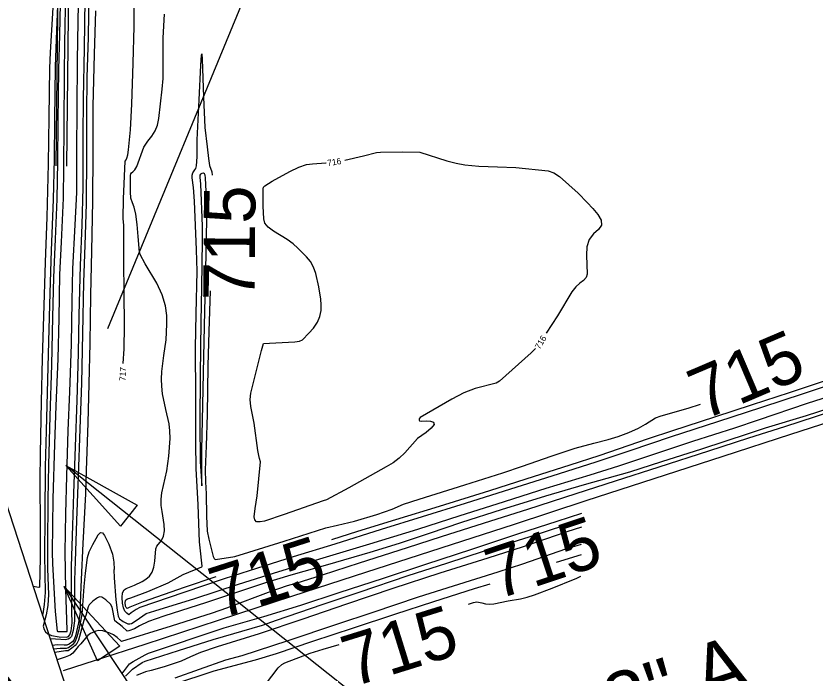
# Model space of a CAD drawing. Extents: x -468563856 to 36492962, y -306094093 to 11899197.
# Drawn here: x 1819091 to 1819604, y 530139 to 530560 of the extents above; entities that cross this region are included whole.
import ezdxf

# ---------------------------------------------------------------- set-up
doc = ezdxf.new("R2010")
doc.units = 0
for name, color, linetype in [('DT_X_Contour_Minor', 7, 'Continuous'), ('DT_X_Terrain_Ground_Line', 7, 'Continuous'), ('Level 14', 7, 'Continuous'), ('Level 19', 7, 'Continuous'), ('Level 40', 7, 'Continuous'), ('Level 56', 7, 'Continuous'), ('SC_Scratch1', 7, 'Continuous')]:
    doc.layers.add(name, color=color, linetype=linetype)

msp = doc.modelspace()

# ---------------------------------------------------------------- linework, layer by layer
at = {"layer": 'DT_X_Contour_Minor'}
for points in [[(1819123.04, 530576.32), (1819122.55, 530542.42), (1819122.31, 530522.38), (1819122, 530490.35), (1819121.92, 530463.26), (1819121.73, 530443.28), (1819120.3, 530415.01), (1819119.32, 530394.3), (1819118.81, 530366.36), (1819118.19, 530340.29), (1819117, 530310.12), (1819116.14, 530285.53), (1819115.1, 530250.53), (1819114.55, 530216.45), (1819114.82, 530208.84), (1819116.5, 530178.28), (1819117.79, 530165.64), (1819118.29, 530165.56), (1819124.21, 530165.45), (1819124.21, 530166.38), (1819123.28, 530192.74), (1819122.92, 530216.31), (1819123.35, 530241.23), (1819123.89, 530265.12), (1819124.89, 530294.25), (1819125.83, 530319.08), (1819126.97, 530349.68), (1819127.46, 530377.53), (1819127.9, 530398.02), (1819129.36, 530426.26), (1819130.32, 530446.96), (1819130.44, 530474.05), (1819130.58, 530500.07), (1819130.9, 530531.68), (1819131.23, 530556.26), (1819131.8, 530590.99)], [(1819120, 530578.27), (1819119.3, 530547.97), (1819118.61, 530525.83), (1819118.2, 530492.3), (1819118.02, 530466.77), (1819117.61, 530442.7), (1819116.5, 530416.88), (1819115.47, 530392.41), (1819114.87, 530366.91), (1819114.09, 530336.37), (1819112.99, 530303.55), (1819112.14, 530272.28), (1819111.86, 530250.18), (1819111.54, 530220.56), (1819111.57, 530205.58), (1819112.19, 530189.28), (1819111.87, 530182.1), (1819110.63, 530176.17), (1819108.87, 530169.01), (1819109.54, 530166.88), (1819110.41, 530165.36), (1819111.89, 530163.98), (1819114.09, 530163.04), (1819119.13, 530162.16), (1819123.77, 530161.98), (1819124.97, 530162.37), (1819125.99, 530163.4), (1819126.77, 530166.01), (1819127.35, 530170.99), (1819127.29, 530178.08), (1819126.89, 530195.65), (1819126.99, 530207.23), (1819127.73, 530233.49), (1819128.41, 530254.03), (1819129.52, 530284.05), (1819130.55, 530313.47), (1819131.51, 530343.93), (1819131.97, 530368.37), (1819132.72, 530400.11), (1819133.86, 530426.25), (1819134.41, 530450.01), (1819134.55, 530482.97), (1819134.67, 530506.95), (1819135.25, 530539.31), (1819135.82, 530570.8)], [(1819138.12, 530576.66), (1819137.58, 530546.32), (1819136.91, 530520.91), (1819136.62, 530497.38), (1819136.57, 530471.07), (1819136.29, 530439.63), (1819135.56, 530413.23), (1819134.74, 530389.39), (1819134.1, 530356.54), (1819133.38, 530324.78), (1819132.38, 530295.36), (1819131.36, 530265.05), (1819130.14, 530236.61), (1819129.28, 530210.39), (1819128.84, 530198.51), (1819128.84, 530187.24), (1819128.96, 530172.36), (1819128.04, 530166.21), (1819126.9, 530162.4), (1819125.89, 530161.24), (1819124.83, 530160.54), (1819123.12, 530160.18), (1819120.11, 530160.35), (1819113.31, 530160.92)], [(1819160.21, 530337.32), (1819160.67, 530346.75), (1819160.95, 530361.36), (1819160.79, 530383.07), (1819160.62, 530402.24), (1819160.49, 530425.65), (1819160.01, 530430.17), (1819160.28, 530442.86), (1819161.4, 530467.08), (1819162.05, 530467.79), (1819162.52, 530468.89), (1819163.05, 530470.93), (1819163.61, 530474.34), (1819164.77, 530487.02), (1819165.67, 530503.5), (1819166.5, 530529.84), (1819167.21, 530553.27), (1819167.2, 530574.75)], [(1819108.42, 530175.98), (1819108.71, 530176.91), (1819109.73, 530182.84), (1819110.24, 530190.48), (1819109.93, 530214.36), (1819110.2, 530239.26), (1819110.33, 530271.05), (1819110.89, 530294.17), (1819111.78, 530326.83), (1819112.53, 530351.29), (1819113.27, 530382.52), (1819114.25, 530409.79), (1819115.54, 530442.4), (1819116.08, 530468.52), (1819116.31, 530493.28), (1819116.76, 530527.55), (1819117.67, 530550.74), (1819118.37, 530572.31)], [(1819114.91, 530565.52), (1819113.34, 530536.57), (1819112.93, 530526.55), (1819112.51, 530495.24), (1819112.03, 530465.36), (1819111.14, 530430.99), (1819110.17, 530402.24), (1819108.96, 530367.73), (1819108.21, 530340.46), (1819107.5, 530312.82), (1819106.86, 530279.6), (1819106.72, 530262.54), (1819106.94, 530231.76), (1819106.86, 530212.96), (1819106.4, 530193.9), (1819106.12, 530193.7), (1819102.44, 530194.41)], [(1819142.3, 530563.39), (1819141.59, 530535.57), (1819140.67, 530502.31), (1819140.65, 530472.82), (1819140.39, 530441.3), (1819139.82, 530409.57), (1819139.25, 530381.18), (1819138.65, 530350.38), (1819138.08, 530324.26), (1819137.45, 530299.3), (1819136.47, 530268.75), (1819135.87, 530253.83), (1819134.31, 530221.88), (1819133.1, 530198.75), (1819132.55, 530183.58), (1819132.53, 530177.88), (1819131.5, 530171.07), (1819129.61, 530162.76), (1819128.7, 530160.4), (1819127.85, 530159.17), (1819125.49, 530157.33), (1819124.01, 530156.69), (1819122.21, 530156.72), (1819117.71, 530156.96), (1819114.73, 530156.54)], [(1819188.16, 530268.57), (1819189.35, 530277.85), (1819190.17, 530289.25), (1819190.04, 530294.13), (1819189.51, 530298.55), (1819187.53, 530307.83), (1819185.4, 530317.9), (1819184.82, 530322.66), (1819184.66, 530327.31), (1819184.9, 530332.11), (1819186.27, 530342.46), (1819187.6, 530352.48), (1819188.12, 530362.43), (1819188, 530368.08), (1819187.2, 530374.35), (1819185.18, 530381.27), (1819181.73, 530388.71), (1819174.31, 530401.27), (1819171.04, 530407.08), (1819170.68, 530408.61), (1819169.79, 530418.73), (1819169.16, 530426.35), (1819168.3, 530433.09), (1819167.17, 530437.47), (1819166.01, 530440.37), (1819165.13, 530443.28), (1819164.74, 530447.26), (1819164.86, 530457.74), (1819165, 530458.93), (1819165.45, 530459.56), (1819166.34, 530460.18), (1819167.53, 530461.35), (1819168.82, 530463.59), (1819173.4, 530476), (1819175.86, 530479.76), (1819178.49, 530483.1), (1819180.7, 530486.4), (1819182.09, 530490.04), (1819182.9, 530494.36), (1819185.1, 530513.04), (1819185.67, 530519.94), (1819185.83, 530532.4), (1819185.85, 530546.09), (1819186.52, 530561.25)], [(1819219.44, 530200.61), (1819199.28, 530193.67), (1819172.84, 530184.48), (1819164.43, 530181.1), (1819162.76, 530180.21), (1819162.04, 530180.89), (1819161.68, 530181.67), (1819161.36, 530184.09), (1819161.5, 530185.19), (1819161.86, 530185.88), (1819162.79, 530186.37), (1819165.03, 530186.99), (1819175.82, 530191.19), (1819189.04, 530196.8), (1819198.64, 530202.02), (1819210.55, 530206.98), (1819210.76, 530207.45), (1819209.38, 530219.13), (1819209.07, 530222.89), (1819208.19, 530246.75), (1819206.96, 530269.89), (1819206.71, 530286.45), (1819206.71, 530315.92), (1819206.46, 530347.38), (1819206.91, 530369.04), (1819207.48, 530396.39), (1819207.16, 530410.08), (1819205.84, 530441.29), (1819205.25, 530450.13), (1819204.28, 530456.25), (1819204.38, 530457.96), (1819204.75, 530459.45), (1819205.99, 530461.42), (1819206.65, 530462.32), (1819207.15, 530463.88), (1819207.46, 530469.69), (1819207.57, 530480.55), (1819208.87, 530506.34), (1819209.88, 530528.57), (1819210.28, 530535.02), (1819210.48, 530535.74), (1819210.75, 530532.25), (1819211.53, 530507.92), (1819212.52, 530488.6), (1819213.95, 530476.08), (1819214.88, 530468.69), (1819215.38, 530464.13), (1819216.91, 530460.21), (1819217.14, 530458.08)], [(1819302.25, 530467.6), (1819314.15, 530470.36), (1819322.56, 530472.43), (1819325.11, 530472.74), (1819339.35, 530472.86), (1819350.26, 530472.72), (1819367.62, 530467.17), (1819373.72, 530465.64), (1819379.15, 530464.63), (1819388.26, 530463.76), (1819400.06, 530463.36), (1819411.97, 530462.98), (1819432.54, 530460.81), (1819436.28, 530459.47), (1819439.89, 530457.08), (1819451.79, 530446.49), (1819457.71, 530440.47), (1819461.23, 530436.65), (1819464.42, 530432.8), (1819466.53, 530429.15), (1819466.8, 530425.91), (1819464.81, 530423.14), (1819461.66, 530420.3), (1819458.81, 530416.73), (1819457.39, 530412), (1819457.14, 530406.72), (1819457.7, 530394.65), (1819456.92, 530392.36), (1819455.21, 530390.58), (1819452.88, 530388.81), (1819450.34, 530386.51), (1819447.89, 530383.23), (1819438.57, 530367.92), (1819431.4, 530356.73)], [(1819424.43, 530346.92), (1819421.63, 530344.23), (1819401.35, 530325.98), (1819399.22, 530324.76), (1819385.83, 530321.23), (1819378.57, 530318.39), (1819370.83, 530314.43), (1819350.56, 530302.63), (1819349.98, 530301.85), (1819349.83, 530301.07), (1819350.19, 530300.53), (1819351.12, 530300.41), (1819354.7, 530300.61), (1819357.16, 530300.42), (1819359.1, 530299.7), (1819359.43, 530298.2), (1819357.5, 530295.83), (1819354.31, 530293.17), (1819348.87, 530289.18), (1819340.74, 530280.09), (1819337.01, 530276.52), (1819333.28, 530273.67), (1819328.8, 530270.96), (1819304.8, 530257.7), (1819290.46, 530249.95), (1819288.38, 530249.29), (1819263.36, 530240.46), (1819250.69, 530236.34), (1819247.87, 530235.75), (1819245.65, 530235.87), (1819244.49, 530237.03), (1819244.2, 530239.03), (1819244.82, 530244.35), (1819245.94, 530252.38), (1819248.13, 530274.28), (1819247.58, 530276.42), (1819247, 530278.34), (1819246.36, 530281.63), (1819244.12, 530298.98), (1819242.06, 530309.83), (1819241.61, 530314.3), (1819241.98, 530318.29), (1819248.83, 530345.66), (1819250.01, 530350.11), (1819253.95, 530350.39), (1819270.1, 530351.18), (1819273.2, 530351.6), (1819275, 530352.44), (1819279.22, 530356.63), (1819282.12, 530359.97), (1819284.67, 530363.68), (1819286.27, 530367.45), (1819287.02, 530371.2), (1819287.15, 530374.91), (1819286.89, 530378.59), (1819285.65, 530386.35), (1819283.75, 530395), (1819282.23, 530399.06), (1819280.16, 530402.57), (1819277.68, 530405.66), (1819272.17, 530411.25), (1819269.05, 530413.98), (1819265.34, 530416.71), (1819256.52, 530422.14), (1819253, 530424.7), (1819251.01, 530427.17), (1819250.21, 530429.95), (1819249.9, 530438.18), (1819249.83, 530449.31), (1819249.99, 530450.31), (1819250.96, 530451.23), (1819255.65, 530454.12), (1819266.89, 530460.41), (1819272.81, 530463.19), (1819277.59, 530464.75), (1819281.61, 530465.37), (1819290.07, 530465.86), (1819290.37, 530465.89)], [(1819210.56, 530258.81), (1819210.6, 530281.72), (1819211.27, 530310.48), (1819211.84, 530341.6), (1819212.37, 530370.91), (1819213.03, 530397.35), (1819213.7, 530429.57), (1819213.65, 530439.09), (1819212.97, 530456.39), (1819212.67, 530458.05), (1819212.23, 530458.93), (1819211.69, 530459.26), (1819210.55, 530459.17), (1819209.67, 530458.72), (1819209.26, 530457.92), (1819209.29, 530456.76), (1819209.62, 530452.13), (1819210.68, 530425.27), (1819210.76, 530416.15), (1819210.32, 530386.1), (1819209.86, 530364.05), (1819209.42, 530330.06), (1819209.33, 530299.39), (1819209.45, 530274.42), (1819210.56, 530258.81)], [(1819215.89, 530383.89), (1819214.99, 530357.75), (1819214.35, 530335.73), (1819213.91, 530304.68), (1819213.22, 530284.62), (1819212.68, 530269.23), (1819212.82, 530261.45), (1819213.38, 530253.75), (1819213.55, 530239.53), (1819213.87, 530229.91), (1819214.96, 530224.73), (1819217.88, 530213.61), (1819218.39, 530212.23), (1819219.02, 530211.74), (1819222.08, 530212.07), (1819231.79, 530213.57), (1819240.63, 530216.34), (1819263.37, 530223.5), (1819290.14, 530231.87), (1819297.63, 530233.69), (1819308.35, 530236.15), (1819322.84, 530240.45), (1819332.62, 530243.95), (1819339.87, 530247.08), (1819349.82, 530250.35), (1819379.25, 530259.52), (1819403.49, 530267.17), (1819416.2, 530271.41), (1819434.56, 530278), (1819449.95, 530282.94), (1819461.96, 530286.23), (1819471.16, 530288.52), (1819477.5, 530290.54), (1819484.43, 530293.08), (1819490.62, 530295.79), (1819495.12, 530298.38), (1819501.5, 530302.48), (1819505.06, 530303.83), (1819522.38, 530308.6), (1819530.24, 530311.17)], [(1819735.12, 530365.57), (1819720.1, 530360.98), (1819690.82, 530351.97), (1819665.02, 530343.81), (1819633.43, 530333.77), (1819616.08, 530328.1), (1819587.14, 530318.56), (1819563.46, 530310.78), (1819539.22, 530302.91), (1819512.34, 530294.19), (1819496.73, 530288.95), (1819465.07, 530278.01), (1819446.56, 530272.1), (1819418.4, 530263.17), (1819394.91, 530255.75), (1819362.75, 530245.73), (1819334.71, 530237.16), (1819310.42, 530229.54), (1819293.76, 530224.31)], [(1819625.91, 530327.72), (1819596.04, 530317.94), (1819569.46, 530309.04), (1819541.27, 530299.92), (1819511.55, 530290.3), (1819484.91, 530281.29), (1819463.25, 530274.01), (1819435, 530265.11), (1819408.56, 530256.74), (1819379.45, 530247.52), (1819351.76, 530238.91), (1819325.44, 530230.82), (1819295.73, 530221.59), (1819269.06, 530213.3), (1819240.93, 530204.45), (1819224.86, 530199.21), (1819199.04, 530190.51), (1819170.76, 530180.86), (1819168.36, 530179.71), (1819165.31, 530177.51), (1819163.79, 530176.28), (1819162.37, 530177.21), (1819161.28, 530178.46), (1819160.27, 530180.6), (1819159.59, 530183.76), (1819159.39, 530187.27), (1819159.77, 530190.3), (1819160.76, 530192.21), (1819162.04, 530193.17), (1819167.47, 530195.13), (1819172.22, 530197.47), (1819174.7, 530198.99), (1819176.94, 530200.92), (1819178.68, 530203.51), (1819179.77, 530206.85), (1819180.33, 530210.5), (1819180.97, 530218.57), (1819181.72, 530220.28), (1819184.69, 530223.91), (1819185.98, 530226.52), (1819186.53, 530230.02), (1819186.43, 530234.1), (1819185.17, 530242.39), (1819184.55, 530246.31), (1819184.38, 530250.25), (1819184.88, 530254.3), (1819188.16, 530268.57)], [(1819399.98, 530247.38), (1819431.34, 530257.29), (1819459.62, 530266.01), (1819477.89, 530271.76), (1819501.59, 530279.71), (1819525.41, 530287.54), (1819552.36, 530296.08), (1819567.56, 530301.08), (1819598.82, 530311.77), (1819616.96, 530317.59)], [(1819629.11, 530313.79), (1819598.14, 530303.81), (1819571.69, 530295.79), (1819560.83, 530292.28), (1819530.85, 530282.37), (1819505.37, 530274.16), (1819484.81, 530267.74), (1819455.67, 530259.51), (1819430.98, 530252.25), (1819402.43, 530243.5), (1819376.99, 530235.31), (1819356.34, 530228.39), (1819336.98, 530221.83), (1819318.28, 530216.16), (1819291.13, 530208.15), (1819267.55, 530201.71), (1819251.29, 530196.76), (1819232.79, 530190.55), (1819213.61, 530184.09), (1819186.15, 530175.35), (1819176.41, 530171.96), (1819170.6, 530169.07), (1819167.46, 530167.29), (1819163.68, 530165.96), (1819162.57, 530165.83), (1819159.46, 530168.82), (1819154.66, 530172.45), (1819153.04, 530181.01), (1819151.9, 530183.01), (1819149.05, 530185.76), (1819146.37, 530187.53), (1819145.01, 530187.68), (1819143.55, 530187.12), (1819143.03, 530186.73), (1819140.64, 530184.91), (1819138.4, 530182.69), (1819137.63, 530181.3), (1819136.2, 530175.74), (1819134.95, 530172.59), (1819133.33, 530166.97), (1819131.45, 530160.04), (1819130.4, 530157.9), (1819129.31, 530156.63), (1819127.11, 530154.9), (1819124.89, 530153.2), (1819123.14, 530153.07), (1819116.2, 530152.01)], [(1819613.71, 530306.27), (1819584.05, 530296.78), (1819561.09, 530289.45), (1819535.37, 530281.14), (1819503.65, 530270.91), (1819475.47, 530261.8), (1819450.39, 530253.78), (1819419.46, 530243.78), (1819395.73, 530236.33), (1819363.91, 530226.17), (1819342.12, 530219.05), (1819311.49, 530209.3), (1819287.76, 530201.58), (1819270.82, 530196.38), (1819265.18, 530194.79), (1819254.88, 530191.18), (1819226.3, 530180.53), (1819217.27, 530177.29), (1819190.84, 530168.94), (1819159.1, 530159.07), (1819158.53, 530159.58), (1819156.25, 530161.63), (1819153.9, 530163.31), (1819151.53, 530164.46), (1819147.16, 530165.98), (1819144.54, 530166.26), (1819142.62, 530165.68), (1819142.21, 530165.56), (1819139.12, 530164.13), (1819137.45, 530162.93), (1819135.85, 530161.33), (1819132.92, 530157.51), (1819131.2, 530156), (1819127.84, 530151.57), (1819126.02, 530150.28), (1819122.89, 530148.96), (1819117.69, 530147.42)], [(1819115.46, 530154.31), (1819119.64, 530154.93), (1819123.88, 530154.87), (1819125.06, 530155.21), (1819128.58, 530157.93), (1819129.6, 530159.39), (1819130.69, 530162.23), (1819131.86, 530166.79), (1819133.79, 530176.47), (1819135.08, 530194.31), (1819135.87, 530202.89), (1819137.31, 530212.9), (1819138.41, 530216.63), (1819140.58, 530221.22), (1819143.82, 530227.1), (1819143.88, 530227.22), (1819145.53, 530228.95), (1819146.94, 530228.79), (1819148.21, 530227.09), (1819150.84, 530221.39), (1819153.21, 530215.09), (1819154.13, 530209.89), (1819154.28, 530205.26), (1819154.2, 530204.99), (1819154.39, 530199.99), (1819155.46, 530185.86), (1819156.16, 530179.26), (1819156.86, 530175.38), (1819157.68, 530173.61), (1819160.17, 530171.92), (1819163.2, 530170.5), (1819164.39, 530170.38), (1819165.5, 530170.74), (1819168.5, 530172.66), (1819174.94, 530176.99), (1819180.38, 530178.73), (1819206.04, 530186.63), (1819234.15, 530195.87), (1819256.4, 530202.86), (1819286.17, 530212.02), (1819318.26, 530221.7), (1819349.14, 530231.17), (1819376.23, 530239.8), (1819399.98, 530247.38)], [(1819159.19, 530138.29), (1819160.27, 530139.66), (1819164.12, 530144.7), (1819166.58, 530146.37), (1819174.24, 530150.66), (1819176.34, 530151.65), (1819185.24, 530154.72), (1819215.3, 530164.7), (1819224.86, 530167.78), (1819250.26, 530175.21), (1819273.96, 530182.49), (1819298.54, 530190.47), (1819326.95, 530199.78), (1819354.24, 530208.64), (1819383.59, 530218.31), (1819413.75, 530228.24), (1819438.35, 530236.27), (1819454.1, 530241.44)], [(1819161.69, 530136.9), (1819166.16, 530141.28), (1819172.19, 530145.6), (1819174.2, 530146.4), (1819195.5, 530153.31), (1819217.91, 530160.35), (1819249.47, 530169.66), (1819258.52, 530172.68), (1819287.81, 530182.78), (1819311.34, 530190.81), (1819342.87, 530201.45), (1819367.55, 530209.41), (1819391.81, 530217.16), (1819420.36, 530226.19), (1819443.33, 530233.73), (1819454.04, 530237.18)], [(1819453.97, 530232.39), (1819444.66, 530229.43), (1819416.69, 530219.84), (1819393.96, 530212.55), (1819363.12, 530202.87), (1819333.09, 530193.01), (1819303.38, 530182.96), (1819275.31, 530173.47), (1819247.35, 530164), (1819220.43, 530155.64), (1819209.73, 530151.95), (1819203.24, 530149.18), (1819197.21, 530146.53), (1819186.43, 530142.89), (1819177.99, 530140.57), (1819174.44, 530139.75), (1819168.75, 530137.42)], [(1819453.8, 530221.33), (1819443.7, 530218.22), (1819416.15, 530208.66), (1819400.42, 530203.49), (1819371.72, 530194.61), (1819349.33, 530187.48), (1819320.29, 530177.73), (1819296.89, 530170), (1819265.65, 530159.58), (1819236.27, 530149.92), (1819225.8, 530147.08), (1819208.93, 530141.2), (1819193.34, 530135.62)], [(1819453.7, 530214.58), (1819437.67, 530209.67)], [(1819381.61, 530183.06), (1819384.73, 530184.03), (1819386.77, 530184.44), (1819390.05, 530183.79), (1819392.47, 530183.3), (1819395.11, 530183.07), (1819397.73, 530183.31), (1819406.93, 530185.08), (1819414.86, 530186.39), (1819419.16, 530187.47), (1819423.85, 530188.96), (1819435.25, 530193.34), (1819449.99, 530199.25), (1819450.62, 530199.38), (1819451.37, 530199.98), (1819453.5, 530201.01)], [(1819395.12, 530195.9), (1819385.15, 530192.77), (1819359, 530184.58), (1819334.03, 530176.41), (1819307.61, 530167.7), (1819281.41, 530159.1), (1819258.24, 530151.29), (1819244.66, 530147.14), (1819218.34, 530140.1), (1819191.64, 530131.27)], [(1819251.34, 530131.53), (1819259.52, 530142.17), (1819261.76, 530144.31), (1819263.86, 530145.54), (1819280.02, 530151.54), (1819288.43, 530154.18), (1819298.6, 530157.18)]]:
    msp.add_lwpolyline(points, dxfattribs=at)
at = {"layer": 'DT_X_Terrain_Ground_Line'}
msp.add_line((1819362.19, 529394.35), (1818754.73, 531265.42), dxfattribs=at)
at = {"layer": 'Level 14'}
for points in [[(1820085.62, 530453.49), (1820043.35, 530439.51), (1820011.97, 530429.33), (1819977.27, 530417.86), (1819932.41, 530403.25), (1819886.48, 530388.28), (1819843.09, 530374.3), (1819797.62, 530359.69), (1819759.78, 530347.43), (1819718.07, 530333.98), (1819677.06, 530320.65), (1819633.68, 530306.46), (1819588.1, 530291.84), (1819544.63, 530277.68), (1819500.45, 530263.45), (1819456.73, 530249.26), (1819410.72, 530234.19), (1819363.8, 530218.94)], [(1819363.8, 530218.94), (1819315.57, 530203.36), (1819268.79, 530188.07), (1819221.06, 530172.52), (1819174.05, 530157.21), (1819142.25, 530146.96), (1819121.63, 530140.31)]]:
    msp.add_lwpolyline(points, dxfattribs=at)
at = {"layer": 'Level 40'}
for p, q in [((1819361.17, 530083.2), (1819123.28, 530271.85)), ((1819158.35, 530233.07), (1819123.28, 530271.85)), ((1819123.28, 530271.85), (1819169.02, 530246.52)), ((1819169.02, 530246.52), (1819158.35, 530233.07)), ((1819143.62, 530146.62), (1819122.3, 530194.35)), ((1819122.3, 530194.35), (1819157.95, 530156.1)), ((1819157.95, 530156.1), (1819143.62, 530146.62))]:
    msp.add_line(p, q, dxfattribs=at)
for points in [[(1819150.23, 530359.68), (1819246.6, 530593.19), (1820032.21, 530848.25)], [(1819122.3, 530194.36), (1819302.66, 529922.19), (1819373.99, 529945.35)]]:
    msp.add_lwpolyline(points, dxfattribs=at)
at = {"layer": 'Level 56'}
for points in [[(1819117.15, 530463.97), (1819118.3, 530560.36), (1819120.08, 530660.34), (1819121.74, 530760.33), (1819122.45, 530810.32), (1819124.48, 530935.11), (1819124.58, 530977.45)], [(1819123.91, 530463.84), (1819125.06, 530560.22), (1819126.84, 530660.2), (1819128.5, 530760.19), (1819129.21, 530810.19), (1819131.24, 530934.97), (1819131.34, 530977.31)]]:
    msp.add_lwpolyline(points, dxfattribs=at)
at = {"layer": 'SC_Scratch1'}
msp.add_lwpolyline([(1818754.73, 531265.42), (1818680.3, 532625.97), (1826365.04, 535120.88), (1826839.27, 533890.33), (1827446.85, 532018.88), (1827532.11, 531348.3), (1819682.53, 528840.07), (1819362.19, 529394.35)], close=True, dxfattribs=at)

# ---------------------------------------------------------------- texts
at = {"layer": 'DT_X_Terrain_Ground_Line'}
msp.add_text('MATCH LINE                  STA. 1525+00', height=46.8, rotation=107.9864, dxfattribs=at).set_placement((1819311.09, 529448.74))
at = {"layer": 'Level 19'}
for s, height, rotation, p in [('716', 4, 9.1501, (1819291.37, 530463.75)), ('715', 33, 89.5516, (1819244.38, 530377.67)), ('715', 33, 23.073, (1819531.99, 530300.67)), ('716', 4, 59.2725, (1819427.22, 530346.01)), ('717', 4, 87.2099, (1819161.66, 530325.98)), ('715', 33, 18.3919, (1819399.56, 530185.77)), ('715', 33, 17.6872, (1819222.22, 530173.6)), ('715', 33, 17.2575, (1819306.97, 530129.72))]:
    msp.add_text(s, height=height, rotation=rotation, dxfattribs=at).set_placement(p)
at = {"layer": 'Level 40'}
msp.add_text('48" A', height=37.5, rotation=17.9864, dxfattribs=at).set_placement((1819449.57, 530091.21))

doc.saveas('drawing.dxf')
